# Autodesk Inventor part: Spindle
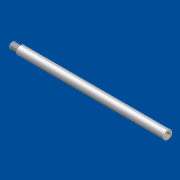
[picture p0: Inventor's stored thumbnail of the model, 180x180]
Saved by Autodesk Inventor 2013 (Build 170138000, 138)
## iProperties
Shininess: 69.0
Length Units: 11269
Angle Units: 11279
Time Units: 11290
Mass Units: 11283
Length Display Precision: 3
Angle Display Precision: 2
Created: 2001-04
Part Number: Spindle
Material: Standard
Document SubType Name: Modellieren
Designer: dl
Density: 1 g/cm^3
Density: 0.0
Volumn: 0.0
Area: 0.0
PropertySet Name: Model Information
Control State: 0
Master: False
Checked Out: False
Author: dl
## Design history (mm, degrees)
body "Solid1"
sketch "Sketch2"
  geometry: L1 (-0.866, 1.5)-(0.866, 1.5); L2 (0.866, 1.5)-(1.732, 0); L3 (1.732, 0)-(0.866, -1.5); L4 (0.866, -1.5)-(-0.866, -1.5); L5 (-0.866, -1.5)-(-1.732, 0); L6 (-1.732, 0)-(-0.866, 1.5); C1 r 2.5 at (0, 0) reference
  constraints: 12 end point, 3 parallel, 1 horizontal
  dimensions: "d9" = 3 distance of L4.end L1.start; "d10" = 0 vertical distance of C1.centre L5.end; "d11" = 3 distance between parallel lines of L5 L2 (= d9); "d12" = 3 distance between parallel lines of L3 L6 (= d9); "d13" = 120 deg angle of L2 L1; "d14" = 120 deg angle of L5 L6 (= d13); "d15" = 1.5 distance from line of L5.end L4 (= 0.5 x d9); "d16" = 1.5 distance from line of C1.centre L2 (= d15)
sketch "Sketch3"
  geometry: C1 r 4 at (0, 0) reference; 1 further point
  constraints: 1 coincident
revolve "Revolution1" stored, may be unused: angle "d4" = 90 deg
thread "Thread1" dims "d5" = 10, "d6" = 0
chamfer "Chamfer1" distance "d7" = 0.5; stored, may be unused: second distance "d8" = 0.5, angle "d32" = 45 deg
extrude "Extrusion1" cut sketch "Sketch2" distance "d17" = 5; taper "d18" = 0 deg
hole "Hole1" sketch "Sketch3" diameter "d19" = 4.917; stored, may be unused: countersink angle "d23" = 60 deg, drill point angle "d25" = 118 deg; dims "d20" = 10, "d21" = 4, "d22" = 2, "d24" = 12
chamfer "Chamfer2" distance "d28" = 0.5; stored, may be unused: second distance "d29" = 0.5, angle "d33" = 45 deg
chamfer "Chamfer3" distance "d30" = 0.2; stored, may be unused: second distance "d31" = 0.2, angle "d34" = 45 deg
sketch "Sketch1"
  geometry: L1 (0, 0)-(0, 3); L2 (0, 3)-(8, 3); L3 (8, 3)-(8, 4); L4 (8, 4)-(146, 4); L5 (146, 4)-(146, 0); L6 (146, 0)-(0, 0)
  constraints: 12 end point, 4 parallel, 1 perpendicular, 1 vertical
  dimensions: "d0" = 8 distance of L1.end L2.end; "d1" = 3 distance of L1.start L1.end; "d2" = 4 distance of L4.end L5.end; "d3" = 146 distance of L5.end L1.start
